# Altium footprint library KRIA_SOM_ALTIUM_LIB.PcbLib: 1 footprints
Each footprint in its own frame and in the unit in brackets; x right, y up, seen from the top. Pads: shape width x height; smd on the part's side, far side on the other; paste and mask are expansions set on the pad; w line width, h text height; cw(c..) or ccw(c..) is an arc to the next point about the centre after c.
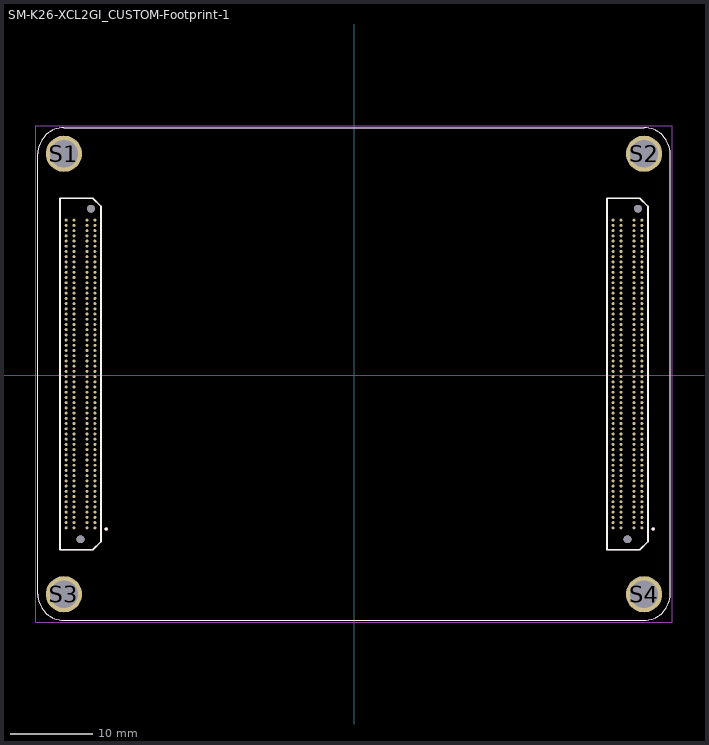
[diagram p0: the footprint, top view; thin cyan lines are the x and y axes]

## SM-K26-XCL2GI_CUSTOM-Footprint-1 [mil]
pads (488):
  round 14.02 smd: A1(-1242.36,-732.5) A2(-1242.36,-707.5) A3(-1242.36,-682.5) A4(-1242.36,-657.5) A5(-1242.36,-632.5) A6(-1242.36,-607.5) A7(-1242.36,-582.5) A8(-1242.36,-557.5) A9(-1242.36,-532.5) A10(-1242.36,-507.5) A11(-1242.36,-482.5) A12(-1242.36,-457.5) A13(-1242.36,-432.5) A14(-1242.36,-407.5) A15(-1242.36,-382.5) A16(-1242.36,-357.5) A17(-1242.36,-332.5) A18(-1242.36,-307.5) A19(-1242.36,-282.5) A20(-1242.36,-257.5) A21(-1242.36,-232.5) A22(-1242.36,-207.5) A23(-1242.36,-182.5) A24(-1242.36,-157.5) A25(-1242.36,-132.5) A26(-1242.36,-107.5) A27(-1242.36,-82.5) A28(-1242.36,-57.5) A29(-1242.36,-32.5) A30(-1242.36,-7.5) A31(-1280.16,-732.5) A32(-1280.16,-707.5) A33(-1280.16,-682.5) A34(-1280.16,-657.5) A35(-1280.16,-632.5) A36(-1280.16,-607.5) A37(-1280.16,-582.5) A38(-1280.16,-557.5) A39(-1280.16,-532.5) A40(-1280.16,-507.5) A41(-1280.16,-482.5) A42(-1280.16,-457.5) A43(-1280.16,-432.5) A44(-1280.16,-407.5) A45(-1280.16,-382.5) A46(-1280.16,-357.5) A47(-1280.16,-332.5) A48(-1280.16,-307.5) A49(-1280.16,-282.5) A50(-1280.16,-257.5) A51(-1280.16,-232.5) A52(-1280.16,-207.5) A53(-1280.16,-182.5) A54(-1280.16,-157.5) A55(-1280.16,-132.5) A56(-1280.16,-107.5) A57(-1280.16,-82.5) A58(-1280.16,-57.5) A59(-1280.16,-32.5) A60(-1280.16,-7.5) B1(-1242.36,17.5) B2(-1242.36,42.5) B3(-1242.36,67.5) B4(-1242.36,92.5) B5(-1242.36,117.5) B6(-1242.36,142.5) B7(-1242.36,167.5) B8(-1242.36,192.5) B9(-1242.36,217.5) B10(-1242.36,242.5) B11(-1242.36,267.5) B12(-1242.36,292.5) B13(-1242.36,317.5) B14(-1242.36,342.5) B15(-1242.36,367.5) B16(-1242.36,392.5) B17(-1242.36,417.5) B18(-1242.36,442.5) B19(-1242.36,467.5) B20(-1242.36,492.5) B21(-1242.36,517.5) B22(-1242.36,542.5) B23(-1242.36,567.5) B24(-1242.36,592.5) B25(-1242.36,617.5) B26(-1242.36,642.5) B27(-1242.36,667.5) B28(-1242.36,692.5) B29(-1242.36,717.5) B30(-1242.36,742.5) B31(-1280.16,17.5) B32(-1280.16,42.5) B33(-1280.16,67.5) B34(-1280.16,92.5) B35(-1280.16,117.5) B36(-1280.16,142.5) B37(-1280.16,167.5) B38(-1280.16,192.5) B39(-1280.16,217.5) B40(-1280.16,242.5) B41(-1280.16,267.5) B42(-1280.16,292.5) B43(-1280.16,317.5) B44(-1280.16,342.5) B45(-1280.16,367.5) B46(-1280.16,392.5) B47(-1280.16,417.5) B48(-1280.16,442.5) B49(-1280.16,467.5) B50(-1280.16,492.5) B51(-1280.16,517.5) B52(-1280.16,542.5) B53(-1280.16,567.5) B54(-1280.16,592.5) B55(-1280.16,617.5) B56(-1280.16,642.5) B57(-1280.16,667.5) B58(-1280.16,692.5) B59(-1280.16,717.5) B60(-1280.16,742.5) C1(-1342.36,-732.5) C2(-1342.36,-707.5) C3(-1342.36,-682.5) C4(-1342.36,-657.5) C5(-1342.36,-632.5) C6(-1342.36,-607.5) C7(-1342.36,-582.5) C8(-1342.36,-557.5) C9(-1342.36,-532.5) C10(-1342.36,-507.5) C11(-1342.36,-482.5) C12(-1342.36,-457.5) C13(-1342.36,-432.5) C14(-1342.36,-407.5) C15(-1342.36,-382.5) C16(-1342.36,-357.5) C17(-1342.36,-332.5) C18(-1342.36,-307.5) C19(-1342.36,-282.5) C20(-1342.36,-257.5) C21(-1342.36,-232.5) C22(-1342.36,-207.5) C23(-1342.36,-182.5) C24(-1342.36,-157.5) C25(-1342.36,-132.5) C26(-1342.36,-107.5) C27(-1342.36,-82.5) C28(-1342.36,-57.5) C29(-1342.36,-32.5) C30(-1342.36,-7.5) C31(-1380.16,-732.5) C32(-1380.16,-707.5) C33(-1380.16,-682.5) C34(-1380.16,-657.5) C35(-1380.16,-632.5) C36(-1380.16,-607.5) C37(-1380.16,-582.5) C38(-1380.16,-557.5) C39(-1380.16,-532.5) C40(-1380.16,-507.5) C41(-1380.16,-482.5) C42(-1380.16,-457.5) C43(-1380.16,-432.5) C44(-1380.16,-407.5) C45(-1380.16,-382.5) C46(-1380.16,-357.5) C47(-1380.16,-332.5) C48(-1380.16,-307.5) C49(-1380.16,-282.5) C50(-1380.16,-257.5) C51(-1380.16,-232.5) C52(-1380.16,-207.5) C53(-1380.16,-182.5) C54(-1380.16,-157.5) C55(-1380.16,-132.5) C56(-1380.16,-107.5) C57(-1380.16,-82.5) C58(-1380.16,-57.5) C59(-1380.16,-32.5) C60(-1380.16,-7.5) D1(-1342.36,17.5) D2(-1342.36,42.5) D3(-1342.36,67.5) D4(-1342.36,92.5) D5(-1342.36,117.5) D6(-1342.36,142.5) D7(-1342.36,167.5) D8(-1342.36,192.5) D9(-1342.36,217.5) D10(-1342.36,242.5) D11(-1342.36,267.5) D12(-1342.36,292.5) D13(-1342.36,317.5) D14(-1342.36,342.5) D15(-1342.36,367.5) D16(-1342.36,392.5) D17(-1342.36,417.5) D18(-1342.36,442.5) D19(-1342.36,467.5) D20(-1342.36,492.5) D21(-1342.36,517.5) D22(-1342.36,542.5) D23(-1342.36,567.5) D24(-1342.36,592.5) D25(-1342.36,617.5) D26(-1342.36,642.5) D27(-1342.36,667.5) D28(-1342.36,692.5) D29(-1342.36,717.5) D30(-1342.36,742.5) D31(-1380.16,17.5) D32(-1380.16,42.5) D33(-1380.16,67.5) D34(-1380.16,92.5) D35(-1380.16,117.5) D36(-1380.16,142.5) D37(-1380.16,167.5) D38(-1380.16,192.5) D39(-1380.16,217.5) D40(-1380.16,242.5) D41(-1380.16,267.5) D42(-1380.16,292.5) D43(-1380.16,317.5) D44(-1380.16,342.5) D45(-1380.16,367.5) D46(-1380.16,392.5) D47(-1380.16,417.5) D48(-1380.16,442.5) D49(-1380.16,467.5) D50(-1380.16,492.5) D51(-1380.16,517.5) D52(-1380.16,542.5) D53(-1380.16,567.5) D54(-1380.16,592.5) D55(-1380.16,617.5) D56(-1380.16,642.5) D57(-1380.16,667.5) D58(-1380.16,692.5) D59(-1380.16,717.5) D60(-1380.16,742.5) E1(1380.16,-732.5) E2(1380.16,-707.5) E3(1380.16,-682.5) E4(1380.16,-657.5) E5(1380.16,-632.5) E6(1380.16,-607.5) E7(1380.16,-582.5) E8(1380.16,-557.5) E9(1380.16,-532.5) E10(1380.16,-507.5) E11(1380.16,-482.5) E12(1380.16,-457.5) E13(1380.16,-432.5) E14(1380.16,-407.5) E15(1380.16,-382.5) E16(1380.16,-357.5) E17(1380.16,-332.5) E18(1380.16,-307.5) E19(1380.16,-282.5) E20(1380.16,-257.5) E21(1380.16,-232.5) E22(1380.16,-207.5) E23(1380.16,-182.5) E24(1380.16,-157.5) E25(1380.16,-132.5) E26(1380.16,-107.5) E27(1380.16,-82.5) E28(1380.16,-57.5) E29(1380.16,-32.5) E30(1380.16,-7.5) E31(1342.36,-732.5) E32(1342.36,-707.5) E33(1342.36,-682.5) E34(1342.36,-657.5) E35(1342.36,-632.5) E36(1342.36,-607.5) E37(1342.36,-582.5) E38(1342.36,-557.5) E39(1342.36,-532.5) E40(1342.36,-507.5) E41(1342.36,-482.5) E42(1342.36,-457.5) E43(1342.36,-432.5) E44(1342.36,-407.5) E45(1342.36,-382.5) E46(1342.36,-357.5) E47(1342.36,-332.5) E48(1342.36,-307.5) E49(1342.36,-282.5) E50(1342.36,-257.5) E51(1342.36,-232.5) E52(1342.36,-207.5) E53(1342.36,-182.5) E54(1342.36,-157.5) E55(1342.36,-132.5) E56(1342.36,-107.5) E57(1342.36,-82.5) E58(1342.36,-57.5) E59(1342.36,-32.5) E60(1342.36,-7.5) F1(1380.16,17.5) F2(1380.16,42.5) F3(1380.16,67.5) F4(1380.16,92.5) F5(1380.16,117.5) F6(1380.16,142.5) F7(1380.16,167.5) F8(1380.16,192.5) F9(1380.16,217.5) F10(1380.16,242.5) F11(1380.16,267.5) F12(1380.16,292.5) F13(1380.16,317.5) F14(1380.16,342.5) F15(1380.16,367.5) F16(1380.16,392.5) F17(1380.16,417.5) F18(1380.16,442.5) F19(1380.16,467.5) F20(1380.16,492.5) F21(1380.16,517.5) F22(1380.16,542.5) F23(1380.16,567.5) F24(1380.16,592.5) F25(1380.16,617.5) F26(1380.16,642.5) F27(1380.16,667.5) F28(1380.16,692.5) F29(1380.16,717.5) F30(1380.16,742.5) F31(1342.36,17.5) F32(1342.36,42.5) F33(1342.36,67.5) F34(1342.36,92.5) F35(1342.36,117.5) F36(1342.36,142.5) F37(1342.36,167.5) F38(1342.36,192.5) F39(1342.36,217.5) F40(1342.36,242.5) F41(1342.36,267.5) F42(1342.36,292.5) F43(1342.36,317.5) F44(1342.36,342.5) F45(1342.36,367.5) F46(1342.36,392.5) F47(1342.36,417.5) F48(1342.36,442.5) F49(1342.36,467.5) F50(1342.36,492.5) F51(1342.36,517.5) F52(1342.36,542.5) F53(1342.36,567.5) F54(1342.36,592.5) F55(1342.36,617.5) F56(1342.36,642.5) F57(1342.36,667.5) F58(1342.36,692.5) F59(1342.36,717.5) F60(1342.36,742.5) G1(1280.16,-732.5) G2(1280.16,-707.5) G3(1280.16,-682.5) G4(1280.16,-657.5) G5(1280.16,-632.5) G6(1280.16,-607.5) G7(1280.16,-582.5) G8(1280.16,-557.5) G9(1280.16,-532.5) G10(1280.16,-507.5) G11(1280.16,-482.5) G12(1280.16,-457.5) G13(1280.16,-432.5) G14(1280.16,-407.5) G15(1280.16,-382.5) G16(1280.16,-357.5) G17(1280.16,-332.5) G18(1280.16,-307.5) G19(1280.16,-282.5) G20(1280.16,-257.5) G21(1280.16,-232.5) G22(1280.16,-207.5) G23(1280.16,-182.5) G24(1280.16,-157.5) G25(1280.16,-132.5) G26(1280.16,-107.5) G27(1280.16,-82.5) G28(1280.16,-57.5) G29(1280.16,-32.5) G30(1280.16,-7.5) G31(1242.36,-732.5) G32(1242.36,-707.5) G33(1242.36,-682.5) G34(1242.36,-657.5) G35(1242.36,-632.5) G36(1242.36,-607.5) G37(1242.36,-582.5) G38(1242.36,-557.5) G39(1242.36,-532.5) G40(1242.36,-507.5) G41(1242.36,-482.5) G42(1242.36,-457.5) G43(1242.36,-432.5) G44(1242.36,-407.5) G45(1242.36,-382.5) G46(1242.36,-357.5) G47(1242.36,-332.5) G48(1242.36,-307.5) G49(1242.36,-282.5) G50(1242.36,-257.5) G51(1242.36,-232.5) G52(1242.36,-207.5) G53(1242.36,-182.5) G54(1242.36,-157.5) G55(1242.36,-132.5) G56(1242.36,-107.5) G57(1242.36,-82.5) G58(1242.36,-57.5) G59(1242.36,-32.5) G60(1242.36,-7.5) H1(1280.16,17.5) H2(1280.16,42.5) H3(1280.16,67.5) H4(1280.16,92.5) H5(1280.16,117.5) H6(1280.16,142.5) H7(1280.16,167.5) H8(1280.16,192.5) H9(1280.16,217.5) H10(1280.16,242.5) H11(1280.16,267.5) H12(1280.16,292.5) H13(1280.16,317.5) H14(1280.16,342.5) H15(1280.16,367.5) H16(1280.16,392.5) H17(1280.16,417.5) H18(1280.16,442.5) H19(1280.16,467.5) H20(1280.16,492.5) H21(1280.16,517.5) H22(1280.16,542.5) H23(1280.16,567.5) H24(1280.16,592.5) H25(1280.16,617.5) H26(1280.16,642.5) H27(1280.16,667.5) H28(1280.16,692.5) H29(1280.16,717.5) H30(1280.16,742.5) H31(1242.36,17.5) H32(1242.36,42.5) H33(1242.36,67.5) H34(1242.36,92.5) H35(1242.36,117.5) H36(1242.36,142.5) H37(1242.36,167.5) H38(1242.36,192.5) H39(1242.36,217.5) H40(1242.36,242.5) H41(1242.36,267.5) H42(1242.36,292.5) H43(1242.36,317.5) H44(1242.36,342.5) H45(1242.36,367.5) H46(1242.36,392.5) H47(1242.36,417.5) H48(1242.36,442.5) H49(1242.36,467.5) H50(1242.36,492.5) H51(1242.36,517.5) H52(1242.36,542.5) H53(1242.36,567.5) H54(1242.36,592.5) H55(1242.36,617.5) H56(1242.36,642.5) H57(1242.36,667.5) H58(1242.36,692.5) H59(1242.36,717.5) H60(1242.36,742.5)
  round 173.86 hole 133.86: S1(-1390.75,1061.1) S2(1390.75,1061.1) S3(-1390.75,-1051.1) S4(1390.75,-1051.1)
  round 37.4 hole 37.4 unplated: S5(-1261.26,797.72) S6(1361.26,797.72) S7(-1311.26,-787.72) S8(1311.26,-787.72)
Top Overlay:
  circle w7.87: c-1188.15,-738.11 r3.94
  circle w7.87: c1434.37,-738.11 r3.94
  lines w5: -1515.75,-1050.91 ccw(c-1390.55,-1050.91) -1390.55,-1176.1 1390.55,-1176.1 ccw(c1390.55,-1050.91) 1515.75,-1050.91 1515.75,1060.91 ccw(c1390.55,1060.91) 1390.55,1186.1 -1390.55,1186.1 ccw(c-1390.55,1060.91) -1515.75,1060.91 -1515.75,-1050.91
  lines w7.87: -1409.68,-837.91 -1252.2,-837.91 -1212.83,-798.54 -1212.83,808.54 -1252.2,847.91 -1409.68,847.91 -1409.68,-837.91 ; 1212.83,-837.91 1370.32,-837.91 1409.68,-798.54 1409.68,808.54 1370.32,847.91 1212.83,847.91 1212.83,-837.91
Mechanical 13:
  circle w7.87: c-1188.15,-738.11 r3.94
  circle w7.87: c1434.37,-738.11 r3.94
  lines w3.94: -1409.68,-837.91 -1409.68,847.91 -1252.2,847.91 -1212.83,808.54 -1212.83,-798.54 -1252.2,-837.91 -1409.68,-837.91 ; 1212.83,-837.91 1212.83,847.91 1370.32,847.91 1409.68,808.54 1409.68,-798.54 1370.32,-837.91 1212.83,-837.91
  lines w5: -1515.75,-1050.91 ccw(c-1390.55,-1050.91) -1390.55,-1176.1 1390.55,-1176.1 ccw(c1390.55,-1050.91) 1515.75,-1050.91 1515.75,1060.91 ccw(c1390.55,1060.91) 1390.55,1186.1 -1390.55,1186.1 ccw(c-1390.55,1060.91) -1515.75,1060.91 -1515.75,-1050.91
Mechanical 15:
  lines w1.97: -1525.59,-1185.94 -1525.59,1195.94 1525.59,1195.94 1525.59,-1185.94 -1525.59,-1185.94
3D body "step_temp.STEP": height 429.13, standoff 0, extent -1515.75,-1176.1 1515.75,1186.1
